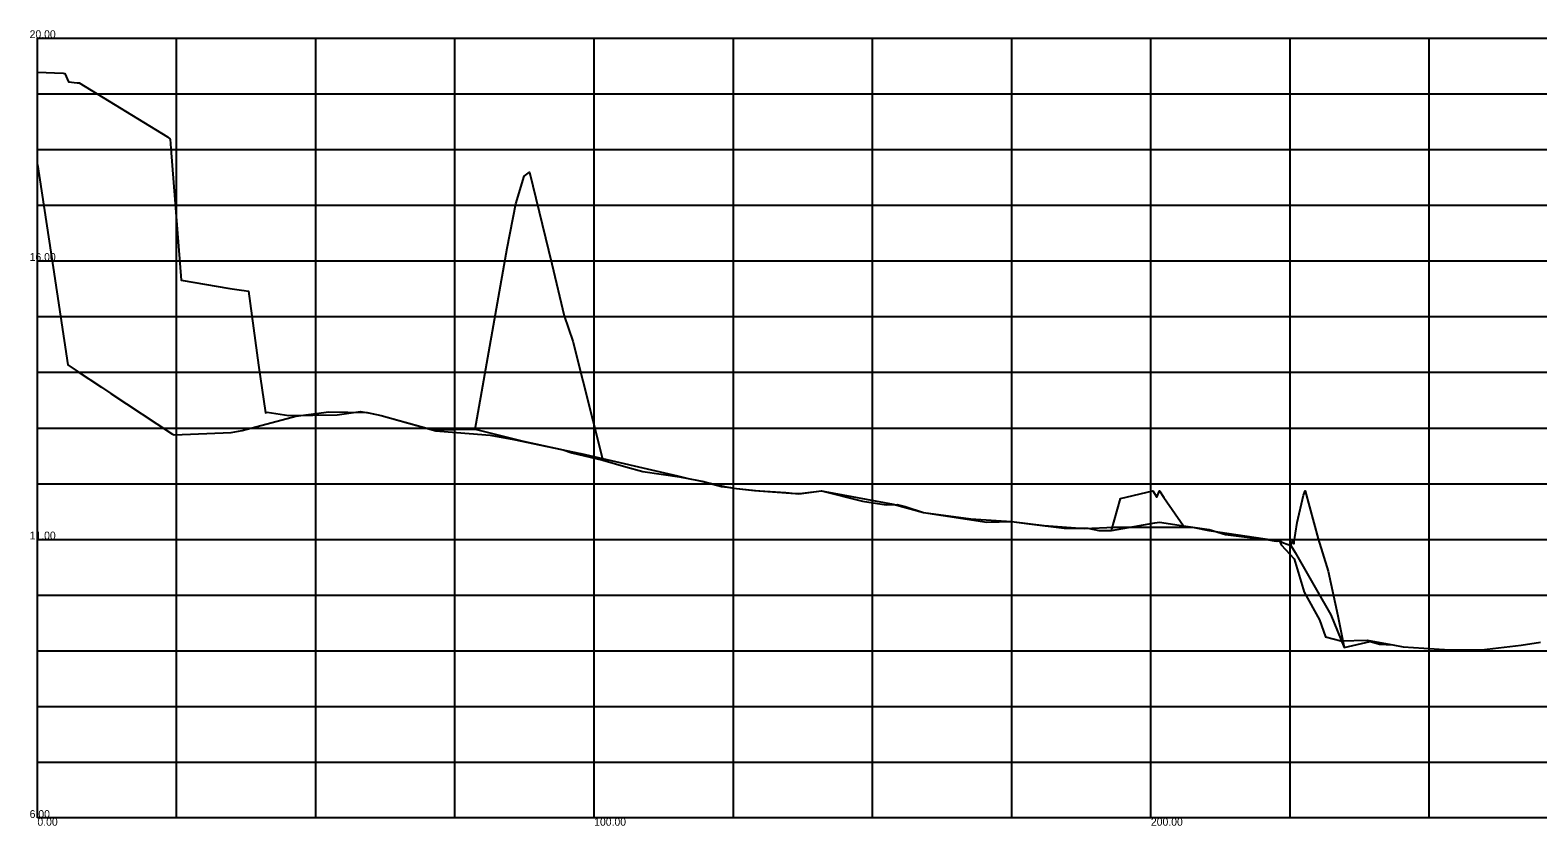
# Model space of a CAD drawing. Extents: x -1 to 1152, y 59 to 201.
# Drawn here: x -1.3 to 269.5, y 58.6 to 201.4 of the extents above; entities that cross this region are included whole.
import ezdxf

# ---------------------------------------------------------------- set-up
doc = ezdxf.new("R2010")
doc.units = 0
doc.layers.add('MAAMUDEL', color=7, linetype='Continuous')

msp = doc.modelspace()

# ---------------------------------------------------------------- linework, layer by layer
at = {"layer": 'MAAMUDEL'}
for p, q in [((25, 60), (25, 200)), ((50, 60), (50, 200)), ((75, 60), (75, 200)), ((100, 60), (100, 200)), ((125, 60), (125, 200)), ((150, 60), (150, 200)), ((175, 60), (175, 200)), ((200, 60), (200, 200)), ((225, 60), (225, 200)), ((250, 60), (250, 200)), ((0, 190), (543.18, 190)), ((0, 180), (543.18, 180)), ((0, 170), (543.18, 170)), ((0, 160), (543.18, 160)), ((0, 150), (543.18, 150)), ((0, 140), (543.18, 140)), ((0, 130), (543.18, 130)), ((0, 120), (543.18, 120)), ((0, 110), (543.18, 110)), ((0, 100), (543.18, 100)), ((0, 90), (543.18, 90)), ((0, 80), (543.18, 80)), ((0, 70), (543.18, 70))]:
    msp.add_line(p, q, dxfattribs=at)
msp.add_lwpolyline([(0, 60), (0, 200), (543.18, 200), (543.18, 60)], close=True, dxfattribs=at)
for points in [[(0, 193.88), (4.62, 193.7), (4.95, 193.63), (5.59, 192.15), (7.13, 191.99), (7.47, 191.96), (23.39, 182.3), (23.87, 181.84), (23.99, 180.16), (25.82, 156.56), (34.53, 155.03), (36.66, 154.74), (37.14, 154.7), (37.92, 154.55), (39.68, 141.31), (40.96, 132.74), (41.27, 132.83), (45.14, 132.25), (53.85, 132.39), (58, 132.98), (59.47, 132.7), (61.72, 132.22), (71.55, 129.49), (73.8, 129.33), (81.31, 128.73), (85.6, 127.93), (97.56, 125.4), (97.58, 125.4), (114.95, 121.42), (116.9, 120.92), (118.76, 120.57), (123.43, 119.52), (125.04, 119.18), (129.58, 118.71), (135.35, 118.33), (136.48, 118.22), (137.39, 118.28), (140.83, 118.7), (148.22, 116.89), (152.46, 116.2), (154.44, 116.26), (155.87, 115.9), (159.13, 114.81), (170.54, 113.09), (174.97, 113.22), (180.82, 112.48), (188.09, 111.96), (193.4, 112.2), (202.87, 112.19), (207.47, 112.2), (210.39, 111.62), (222.11, 109.85), (222.5, 109.78), (222.83, 109.74), (223.1, 109.75), (223.42, 109.03), (225.72, 106.53), (227.55, 100.52), (230.29, 95.58), (231.35, 92.51), (234.1, 91.82), (238.83, 91.9), (243.47, 91.09), (245.3, 90.73), (252.71, 90.23), (259.37, 90.2), (266.51, 91.04), (269.98, 91.54)], [(0, 177.3), (2.8, 158.83), (5.45, 141.36), (7.13, 140.23), (11.5, 137.31), (13.21, 136.19), (24.28, 128.92), (24.54, 128.79), (34.8, 129.19), (36.75, 129.56), (46.41, 132.15), (52.36, 132.89), (59.22, 132.79), (61.72, 132.22), (71.04, 129.67), (74.78, 129.76), (78.64, 129.79), (87.26, 127.61), (94.46, 126.07), (96, 125.54), (101.56, 124.23), (105.68, 123.02), (108.76, 122.18), (115.32, 121.24), (116.9, 120.92), (118.76, 120.59), (119.67, 120.39), (121.33, 119.9), (122.9, 119.5), (124.46, 119.32), (125.04, 119.19), (128.81, 118.8), (134.43, 118.41), (136.79, 118.16), (140.83, 118.7), (140.83, 118.7), (141.43, 118.59), (153.73, 116.34), (159.13, 114.81), (167.65, 113.71), (174.97, 113.22), (178.16, 112.79), (184.42, 112), (188.67, 112.02), (190.66, 111.57), (192.93, 111.6), (193.91, 111.8), (200.68, 112.97), (201.56, 113.07), (205.85, 112.43), (210.46, 111.77), (213.37, 110.91), (221.13, 109.91), (222.11, 109.77), (222.62, 109.71), (222.74, 109.74), (222.83, 109.74), (223.08, 109.75), (223.14, 109.73), (223.84, 109.41), (225.11, 108.93), (225.9, 107.65), (229.73, 100.92), (232.3, 96.48), (234.71, 90.58), (239.41, 91.69), (241.07, 91.2), (243.47, 91.09), (245.3, 90.73), (252.71, 90.23), (259.37, 90.2), (266.51, 91.04), (268.39, 91.3), (269.98, 91.54)], [(0, 177.3), (2.8, 158.83), (5.45, 141.36), (7.13, 140.23), (11.5, 137.31), (13.21, 136.19), (24.28, 128.92), (24.54, 128.79), (34.8, 129.19), (36.75, 129.56), (46.41, 132.15), (52.36, 132.89), (59.22, 132.79), (61.72, 132.22), (71.04, 129.67), (74.78, 129.76), (78.64, 129.79), (84.36, 162.26), (85.95, 170.27), (87.4, 175.23), (88.41, 175.95), (92.37, 159.47), (94.63, 150.12), (96.17, 145.61), (101.56, 124.23), (105.68, 123.02), (108.76, 122.18), (115.32, 121.24), (116.9, 120.92), (118.76, 120.59), (119.67, 120.39), (121.33, 119.9), (122.9, 119.5), (124.46, 119.32), (125.04, 119.19), (128.81, 118.8), (134.43, 118.41), (136.79, 118.16), (140.83, 118.7), (140.83, 118.7), (141.43, 118.59), (153.73, 116.34), (159.13, 114.81), (167.65, 113.71), (174.97, 113.22), (178.16, 112.79), (184.42, 112), (188.67, 112.02), (190.66, 111.57), (192.93, 111.6), (194.55, 117.36), (200.32, 118.7), (201.05, 117.59), (201.53, 118.72), (202.35, 117.5), (205.85, 112.43), (210.46, 111.77), (213.37, 110.91), (221.13, 109.91), (222.11, 109.77), (222.62, 109.71), (222.74, 109.74), (222.83, 109.74), (223.08, 109.75), (223.14, 109.73), (223.84, 109.41), (225.11, 108.93), (225.56, 110.01), (225.7, 109.18), (226.25, 113.01), (227.4, 117.97), (227.73, 118.74), (230.05, 110.1), (231.83, 104.31), (233.58, 96.26), (234.71, 90.58), (239.41, 91.69), (241.07, 91.2), (243.47, 91.09), (245.3, 90.73), (252.71, 90.23), (259.37, 90.2), (266.51, 91.04), (268.39, 91.3), (269.98, 91.54)]]:
    msp.add_lwpolyline(points, dxfattribs=at)

# ---------------------------------------------------------------- texts
for s, p in [('20.00', (-1.4, 200)), ('16.00', (-1.4, 160)), ('11.00', (-1.4, 110)), ('6.00', (-1.4, 60)), ('0.00', (0, 58.6)), ('100.00', (100, 58.6)), ('200.00', (200, 58.6))]:
    msp.add_text(s, height=1.4, dxfattribs=at).set_placement(p)

doc.saveas('drawing.dxf')
